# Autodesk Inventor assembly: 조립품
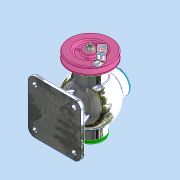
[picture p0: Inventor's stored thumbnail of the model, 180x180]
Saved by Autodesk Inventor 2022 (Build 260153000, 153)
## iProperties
Created: 2024-04
Part Number: 조립품
Document SubType Name: Assembly
Designer: Admin
Author: Admin
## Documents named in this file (16)
- C:\Users\Admin\Desktop\740406V1002\조립품.iam
- C:\Users\Admin\Desktop\740406V1002\본체.ipt
- C:\Users\Admin\Desktop\740406V1002\부품\앞커버.ipt
- C:\Users\Admin\Desktop\740406V1002\부품\뒤커버.ipt
- C:\Users\Admin\Desktop\740406V1002\부품\베어링- 6202.ipt
- KS B 2023 - 6202 - 15 x 35 x 11 - 7.8.ipt
- C:\Users\Admin\Desktop\740406V1002\부품\칼라.ipt
- C:\Users\Admin\Desktop\740406V1002\부품\편심축.ipt
- C:\Users\Admin\Desktop\740406V1002\부품\볼트 M4 x 16.ipt
- C:\Users\Admin\Desktop\740406V1002\부품\키 4 x 4 x 12.ipt
- C:\Users\Admin\Desktop\740406V1002\부품\V-벨트풀리.ipt
- C:\Users\Admin\Desktop\740406V1002\부품\너트 M8.ipt
- C:\Users\Admin\Desktop\740406V1002\부품\슬라이드.ipt
- C:\Users\Admin\Desktop\740406V1002\부품\상부커버.ipt
- C:\Users\Admin\Desktop\740406V1002\부품\오일실 15 30 7.ipt
- C:\Users\Admin\Desktop\740406V1002\부품\볼트 M4 x 12.ipt
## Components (15 placed, 4 different names)
1. KS B 2023 - 6202 - 15 x 35 x 11 - 7.8:1
2. KS B 2023 - 6202 - 15 x 35 x 11 - 7.8:2
3. ISO 4762 M4 x 16:1
4. ISO 4762 M4 x 16:2
5. ISO 4762 M4 x 16:3
6. ISO 4762 M4 x 16:4
7. ISO 4762 M4 x 16:5
8. ISO 4762 M4 x 16:6
9. ISO 4762 M4 x 16:7
10. ISO 4762 M4 x 16:8
11. V-벨트풀리:1
12. KS B 1021 - 에 따름 ISO 1207 - 미터 A  M 4 x 12:1
13. KS B 1021 - 에 따름 ISO 1207 - 미터 A  M 4 x 12:2
14. KS B 1021 - 에 따름 ISO 1207 - 미터 A  M 4 x 12:3
15. KS B 1021 - 에 따름 ISO 1207 - 미터 A  M 4 x 12:4
